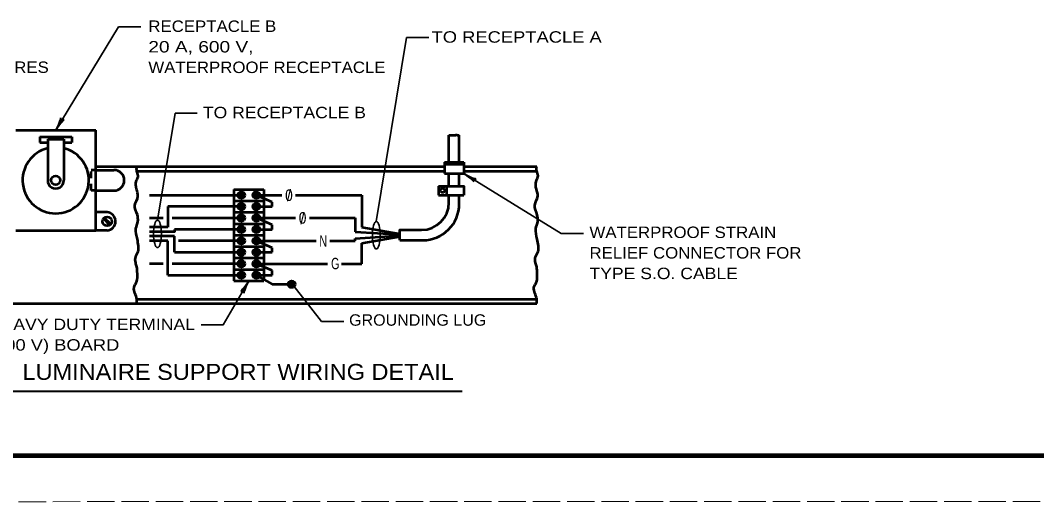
# Model space of a CAD drawing. Extents: x -1 to 679, y 0 to 440.
# Drawn here: x 110.4 to 332.8, y -0.4 to 105 of the extents above; entities that cross this region are included whole.
import ezdxf
from ezdxf.enums import TextEntityAlignment as Align

# ---------------------------------------------------------------- set-up
doc = ezdxf.new("R2010")
doc.units = 0
doc.linetypes.add('LONG_DASHED', pattern=[7.5, 6, -1.5])
doc.linetypes.add('SHORT_DASHED', pattern=[2.7, 1.5, -1.2])
doc.layers.add('1', color=7, linetype='Continuous', lineweight=35)
doc.layers.add('61', color=7, linetype='Continuous', lineweight=35)

msp = doc.modelspace()

# ---------------------------------------------------------------- hatches: boundary and pattern name
at = {"layer": '1'}
for points in [[(159.565, 66.709, 1), (158.065, 66.709, 1)], [(162.815, 66.709, 1), (161.315, 66.709, 1)], [(159.565, 64.209, 1), (158.065, 64.209, 1)], [(162.815, 64.209, 1), (161.315, 64.209, 1)], [(159.565, 61.709, 1), (158.065, 61.709, 1)], [(162.815, 61.709, 1), (161.315, 61.709, 1)], [(159.565, 59.209, 1), (158.065, 59.209, 1)], [(162.815, 59.209, 1), (161.315, 59.209, 1)], [(159.565, 56.709, 1), (158.065, 56.709, 1)], [(162.815, 56.709, 1), (161.315, 56.709, 1)], [(159.565, 54.209, 1), (158.065, 54.209, 1)], [(162.815, 54.209, 1), (161.315, 54.209, 1)], [(159.565, 51.709, 1), (158.065, 51.709, 1)], [(162.815, 51.709, 1), (161.315, 51.709, 1)], [(159.565, 49.209, 1), (158.065, 49.209, 1)], [(162.815, 49.209, 1), (161.315, 49.209, 1)], [(170.565, 47.209, 1), (169.065, 47.209, 1)]]:
    msp.add_hatch(color=256, dxfattribs=at).paths.add_polyline_path(points)

# ---------------------------------------------------------------- linework, layer by layer
for p, q in [((118.19, 80.959), (131.948, 103.541)), ((136.806, 103.541), (131.948, 103.541)), ((188.327, 60.927), (194.971, 101.232)), ((199.829, 101.232), (194.971, 101.232)), ((140.454, 61.219), (144.312, 84.621)), ((149.169, 84.621), (144.312, 84.621)), ((207.484, 71.459), (228.813, 58.324)), ((233.671, 58.324), (228.813, 58.324)), ((170.345, 46.678), (176.344, 39.074)), ((181.202, 39.074), (176.344, 39.074))]:
    msp.add_line(p, q, dxfattribs=at)
at = {"layer": '1', "lineweight": 53}
for p, q in [((109.44, 80.959), (126.94, 80.959)), ((126.94, 58.959), (126.94, 80.959)), ((114.69, 79.459), (121.69, 79.459)), ((114.69, 79.459), (114.69, 78.209)), ((114.69, 78.209), (116.44, 78.209)), ((116.44, 78.959), (116.44, 69.959)), ((116.44, 78.959), (119.94, 78.959)), ((119.94, 78.959), (119.94, 69.959)), ((119.94, 78.209), (121.69, 78.209)), ((121.69, 79.459), (121.69, 78.209)), ((204.234, 73.959), (204.234, 79.832)), ((206.484, 73.959), (206.484, 79.832)), ((203.234, 73.959), (207.484, 73.959)), ((203.234, 73.959), (203.234, 71.459)), ((203.234, 73.459), (207.484, 73.459)), ((207.484, 73.959), (207.484, 71.459)), ((126.94, 72.959), (135.94, 72.959)), ((126.94, 72.209), (130.94, 72.209)), ((135.94, 72.959), (203.234, 72.959)), ((135.94, 71.959), (203.234, 71.959)), ((203.234, 71.459), (207.484, 71.459)), ((204.234, 68.709), (204.234, 71.459)), ((206.484, 68.709), (206.484, 71.459)), ((207.484, 72.959), (223.44, 72.959)), ((207.484, 71.959), (223.44, 71.959)), ((126.94, 67.709), (130.94, 67.709)), ((157.19, 67.959), (163.69, 67.959)), ((163.69, 67.959), (163.69, 47.959)), ((201.949, 68.709), (201.949, 66.709)), ((203.699, 68.709), (203.699, 66.709)), ((138.69, 66.709), (158.065, 66.709)), ((157.19, 65.459), (163.69, 65.459)), ((165.565, 65.209), (162.065, 66.709)), ((162.815, 66.709), (167.69, 66.709)), ((165.565, 64.209), (165.565, 65.209)), ((170.69, 66.709), (185.19, 66.709)), ((185.19, 66.709), (185.19, 59.709)), ((201.949, 66.709), (207.484, 66.709)), ((204.234, 65.082), (204.234, 66.709)), ((206.484, 64.832), (206.484, 66.709)), ((129.44, 62.959), (126.94, 62.959)), ((158.815, 64.209), (142.69, 64.209)), ((142.69, 64.209), (142.69, 59.709)), ((157.19, 62.959), (163.69, 62.959)), ((162.065, 64.209), (165.565, 64.209)), ((130.053, 60.169), (128.65, 61.572)), ((130.23, 60.346), (128.826, 61.749)), ((138.69, 61.709), (141.69, 61.709)), ((143.69, 61.709), (159.565, 61.709)), ((157.19, 60.459), (163.69, 60.459)), ((165.565, 60.209), (162.065, 61.709)), ((162.815, 61.709), (170.69, 61.709)), ((165.565, 59.209), (165.565, 60.209)), ((173.69, 61.709), (183.69, 61.709)), ((183.69, 61.709), (183.69, 58.709)), ((109.44, 58.959), (126.94, 58.959)), ((129.44, 58.959), (126.94, 58.959)), ((142.69, 59.709), (138.69, 59.709)), ((158.815, 59.209), (144.19, 59.209)), ((157.19, 57.959), (163.69, 57.959)), ((162.065, 59.209), (165.565, 59.209)), ((183.69, 58.709), (193.484, 58.07)), ((183.69, 57.209), (193.484, 57.848)), ((185.19, 59.709), (193.484, 58.257)), ((144.19, 57.709), (138.69, 57.709)), ((142.69, 56.709), (138.69, 56.709)), ((142.69, 49.209), (142.69, 56.709)), ((144.19, 54.209), (144.19, 57.709)), ((158.815, 56.709), (145.073, 56.709)), ((162.065, 56.709), (175.19, 56.709)), ((165.565, 55.209), (162.065, 56.709)), ((178.19, 56.709), (183.69, 56.709)), ((183.69, 56.709), (183.69, 57.209)), ((185.19, 56.209), (193.484, 57.66)), ((185.19, 51.709), (185.19, 56.209)), ((193.484, 56.832), (198.484, 56.832)), ((144.19, 54.209), (159.565, 54.209)), ((157.19, 55.459), (163.69, 55.459)), ((162.065, 54.209), (165.565, 54.209)), ((165.565, 54.209), (165.565, 55.209)), ((141.69, 51.709), (138.69, 51.709)), ((158.815, 51.709), (143.69, 51.709)), ((157.19, 52.959), (163.69, 52.959)), ((162.065, 51.709), (177.69, 51.709)), ((165.565, 50.209), (162.065, 51.709)), ((180.69, 51.709), (185.19, 51.709)), ((142.69, 49.209), (158.065, 49.209)), ((157.19, 50.459), (163.69, 50.459)), ((162.065, 49.209), (165.565, 49.209)), ((162.065, 49.209), (165.565, 47.209)), ((165.565, 49.209), (165.565, 50.209)), ((157.19, 47.959), (163.69, 47.959)), ((165.565, 47.209), (169.815, 47.209)), ((135.94, 43.959), (223.44, 43.959))]:
    msp.add_line(p, q, dxfattribs=at)
at = {"layer": '1', "linetype": 'SHORT_DASHED', "lineweight": 53}
msp.add_line((126.94, 72.209), (125.94, 72.209), dxfattribs=at)
at = {"layer": '1', "lineweight": 40}
msp.add_line((107.891, 23.773), (207.154, 23.773), dxfattribs=at)
at = {"layer": '1', "linetype": 'SHORT_DASHED', "lineweight": 53}
msp.add_lwpolyline([(126.94, 67.709), (125.94, 67.709), (125.94, 72.209)], dxfattribs=at)
at = {"layer": '1', "lineweight": 53}
for points in [[(157.19, 67.959), (157.19, 65.459), (157.19, 62.959), (157.19, 60.459), (157.19, 57.959), (157.19, 55.459), (157.19, 52.959), (157.19, 50.459), (157.19, 47.959)], [(201.949, 68.709), (207.484, 68.709), (207.484, 66.709)], [(144.19, 59.209), (144.19, 58.709), (138.69, 58.709)], [(193.484, 56.832), (193.484, 59.082), (198.234, 59.082)], [(100.44, 42.959), (135.94, 42.959), (223.44, 42.959)]]:
    msp.add_lwpolyline(points, dxfattribs=at)
at = {"layer": '1'}
msp.add_lwpolyline([(160.44, 47.959), (154.845, 38.322), (149.988, 38.322)], dxfattribs=at)
at = {"layer": '1', "lineweight": 53}
for centre, radius in [((118.19, 69.959), 1), ((158.815, 66.709), 0.75), ((162.065, 66.709), 0.75), ((202.82, 67.755), 0.469), ((158.815, 64.209), 0.75), ((162.065, 64.209), 0.75), ((158.815, 61.709), 0.75), ((162.065, 61.709), 0.75), ((129.44, 60.959), 1), ((158.815, 59.209), 0.75), ((162.065, 59.209), 0.75), ((158.815, 56.709), 0.75), ((162.065, 56.709), 0.75), ((158.815, 54.209), 0.75), ((162.065, 54.209), 0.75), ((158.815, 51.709), 0.75), ((162.065, 51.709), 0.75), ((158.815, 49.209), 0.75), ((162.065, 49.209), 0.75), ((169.815, 47.209), 0.75)]:
    msp.add_circle(centre, radius, dxfattribs=at)
for centre, radius, start, end in [((118.19, 69.959), 7.25, 103.96796, 76.03204), ((130.927, 69.959), 2.25, 270.32096, 89.67903), ((118.19, 69.917), 1.75, 178.63927, 1.36073), ((198.234, 65.082), 6, 270, 0), ((198.484, 64.832), 8, 270, 0), ((129.296, 60.959), 2.005, 274.11743, 85.88256)]:
    msp.add_arc(centre, radius, start, end, dxfattribs=at)
at = {"layer": '1', "lineweight": 40}
for centre, major_axis, ratio, start_param, end_param in [((118.521, 82.034), (-0.796, -1.606), 0.122415, 0.8963533, 3.1415927), ((118.521, 82.034), (-0.796, -1.606), 0.122415, 0.8963533, 3.1415927), ((118.953, 81.806), (1.064, 1.409), 0.07063, 6.2823074, 8.5597026), ((118.953, 81.806), (1.064, 1.409), 0.07063, 6.2823074, 8.5597026), ((208.327, 70.691), (1.403, -1.071), 0.07063, 6.2823074, 8.5597026), ((208.327, 70.691), (1.403, -1.071), 0.07063, 6.2823074, 8.5597026), ((208.558, 71.122), (-1.602, 0.803), 0.122415, 0.8963533, 3.1415927), ((208.558, 71.122), (-1.602, 0.803), 0.122415, 0.8963533, 3.1415927), ((159.694, 47.096), (-1.034, -1.431), 0.07063, 6.2823074, 8.5597026), ((160.131, 46.876), (0.761, 1.623), 0.122415, 0.8963533, 3.1415927)]:
    msp.add_ellipse(centre, major_axis=major_axis, ratio=ratio, start_param=start_param, end_param=end_param, dxfattribs=at)
at = {"layer": '1'}
for centre in [(140.454, 58.219), (188.327, 57.927)]:
    msp.add_ellipse(centre, major_axis=(0, -3), ratio=0.286071, dxfattribs=at)
at = {"layer": '1', "lineweight": 53}
for points in [[(204.234, 79.832), (204.351, 79.812), (204.471, 79.818), (204.626, 79.847), (204.718, 79.847), (204.821, 79.841), (204.936, 79.858), (205.045, 79.858), (205.235, 79.858), (205.303, 79.87), (205.435, 79.864), (205.63, 79.835), (205.699, 79.875), (205.814, 79.91), (205.952, 79.881), (206.038, 79.835), (206.147, 79.829), (206.267, 79.818), (206.348, 79.818), (206.484, 79.832)], [(135.94, 42.959), (135.94, 43.959), (135.326, 46.48), (135.927, 47.864), (136.047, 49.489), (135.927, 51.053), (135.686, 51.895), (135.686, 53.219), (136.228, 54.362), (136.288, 55.626), (136.047, 57.07), (135.747, 59.416), (136.168, 60.921), (136.047, 62.365), (135.506, 64.531), (136.168, 66.456), (135.867, 68.02), (135.867, 69.886), (136.228, 70.969), (135.94, 71.959), (135.94, 72.959)], [(223.44, 42.959), (223.44, 43.959), (222.826, 46.48), (223.427, 47.864), (223.547, 49.489), (223.427, 51.053), (223.186, 51.895), (223.186, 53.219), (223.728, 54.362), (223.788, 55.626), (223.547, 57.07), (223.247, 59.416), (223.668, 60.921), (223.547, 62.365), (223.006, 64.531), (223.668, 66.456), (223.367, 68.02), (223.367, 69.886), (223.728, 70.969), (223.44, 71.959), (223.44, 72.959)]]:
    msp.add_spline(points, degree=3, dxfattribs=at)
at = {"layer": '61', "lineweight": 158}
msp.add_line((667.635, 9.605), (28.575, 9.625), dxfattribs=at)
at = {"layer": '61', "linetype": 'LONG_DASHED', "lineweight": 13}
msp.add_line((678.575, -0.375), (-1.485, -0.395), dxfattribs=at)

# ---------------------------------------------------------------- texts
at = {"layer": '1'}
for s, width, p in [('RECEPTACLE B', 1.1, (138.458, 102.445)), ('20 A, 600 V,', 1.25, (138.458, 97.945)), ('WATERPROOF RECEPTACLE', 1.1, (138.458, 93.445)), ('WATERPROOF STRAIN', 1.1, (234.977, 57.328)), ('RELIEF CONNECTOR FOR', 1.1, (234.977, 52.828)), ('TYPE S.O. CABLE', 1.15, (234.977, 48.328)), ('HEAVY DUTY TERMINAL', 1.15, (103.579, 37.176)), ('(600 V) BOARD', 1.2, (103.579, 32.676))]:
    msp.add_text(s, height=2.5, dxfattribs=dict(at, width=width)).set_placement(p)
for s, height, width, p in [('TO RECEPTACLE A', 2.5, 1.2, (219.041, 100.086)), ('TO LUMINAIRES', 2.5, 1.1, (102.376, 93.468)), ('TO RECEPTACLE B', 2.5, 1.15, (168.226, 83.543)), ('0', 2.5, 0.9, (169.219, 65.434)), ('0', 2.5, 0.9, (172.206, 60.47)), ('N', 2.5, 0.7, (176.712, 55.426)), ('G', 2.5, 0.7, (179.358, 50.489)), ('GROUNDING LUG', 2.5, 1.05, (197.392, 38.125)), ('LUMINAIRE SUPPORT WIRING DETAIL', 3.5, 1.1, (158.106, 26.273))]:
    msp.add_text(s, height=height, dxfattribs=dict(at, width=width)).set_placement(p, align=Align.CENTER)
for p in [(169.219, 65.391), (172.178, 60.386)]:
    msp.add_text('/', height=2.5, dxfattribs=at).set_placement(p, align=Align.CENTER)

doc.saveas('drawing.dxf')
